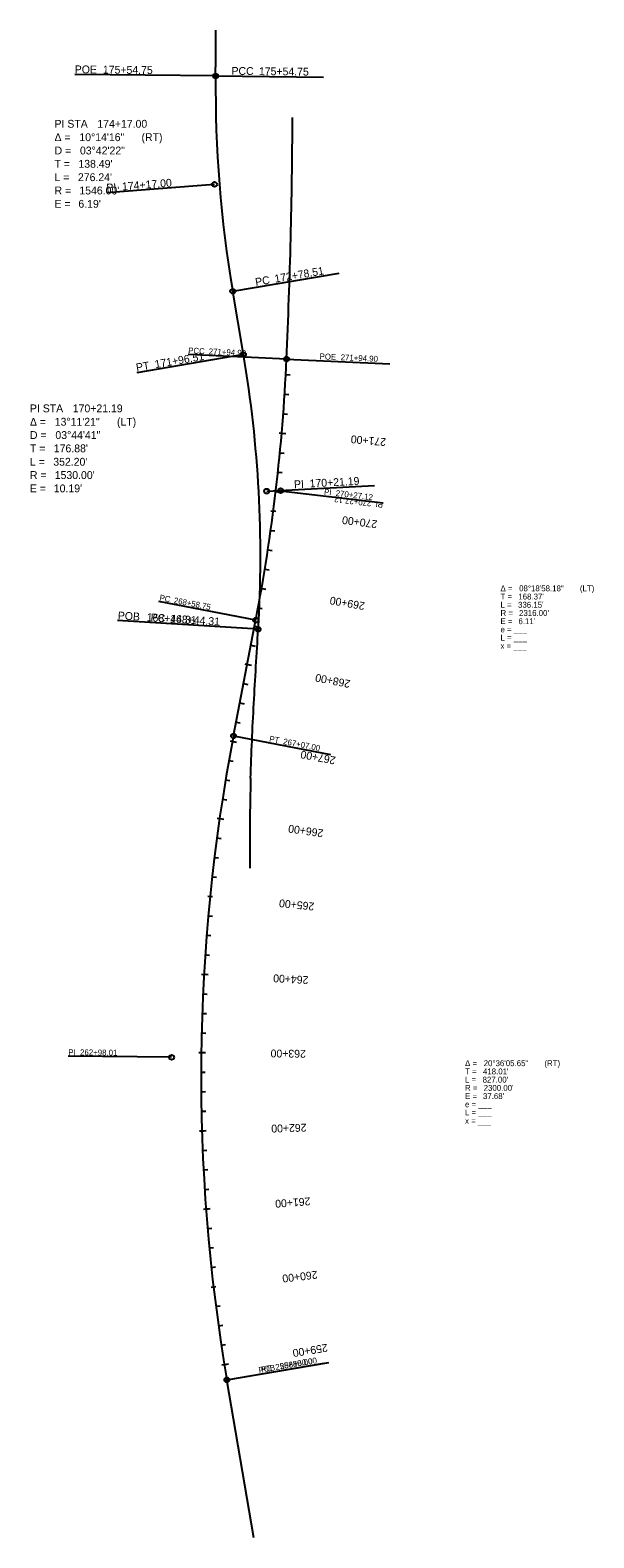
# Model space of a CAD drawing. Extents: x 11526303 to 11527023, y 9594193 to 9596119.
import ezdxf

# ---------------------------------------------------------------- set-up
doc = ezdxf.new("R2010")
doc.units = 0
for name, color, linetype in [('Alignment', 7, 'Continuous'), ('Default', 7, 'Continuous'), ('Draft_2', 7, 'Continuous'), ('Draft_5', 7, 'Continuous'), ('TextAlignment', 7, 'Continuous'), ('TextAlignmentLrg', 7, 'Continuous'), ('TextAlignmentSml', 7, 'Continuous')]:
    doc.layers.add(name, color=color, linetype=linetype)

msp = doc.modelspace()

# ---------------------------------------------------------------- linework, layer by layer
at = {"layer": 'Alignment'}
for p, q in [((11526575.7, 9595704.1), (11526562, 9595785)), ((11526563, 9595217), (11526591.6, 9595366))]:
    msp.add_line(p, q, dxfattribs=at)
for centre, radius, start, end in [((11528086.1, 9596044.3), 1546, 179.4211, 189.6588), ((11525067.4, 9595447.4), 1530, 356.4695, 9.6588), ((11524317.1, 9595802.4), 2316, 349.1117, 357.4279), ((11528821.6, 9594782.5), 2300, 169.1117, 189.7133)]:
    msp.add_arc(centre, radius, start, end, dxfattribs=at)
at = {"layer": 'Default'}
msp.add_line((11526589.1, 9594192.7), (11526554.5, 9594394.5), dxfattribs=at)
for centre, radius, start, end in [((11518903.1, 9596137.1), 7637.4, 359.42082, 359.86053), ((11518997, 9596041.3), 7641.4, 357.42787, 359.74097), ((11529462.5, 9595081), 2878.8, 178.3649, 180.6529)]:
    msp.add_arc(centre, radius, start, end, dxfattribs=at)
msp.add_open_spline([(11526584.9, 9595163.1), (11526585.4, 9595179), (11526586.5, 9595210.7), (11526588.9, 9595258.3), (11526591.6, 9595305.8), (11526593.6, 9595337.5), (11526594.5, 9595353.3)], degree=3, dxfattribs=at)
at = {"layer": 'Draft_2'}
msp.add_line((11526563, 9595217), (11526591.6, 9595366), dxfattribs=at)
msp.add_arc((11528821.6, 9594782.5), 2300, 169.1117, 189.7133, dxfattribs=at)
at = {"layer": 'Draft_5'}
msp.add_line((11526563, 9595217), (11526591.6, 9595366), dxfattribs=at)
for centre, radius, start, end in [((11524317.1, 9595802.4), 2316, 349.1117, 357.4279), ((11528821.6, 9594782.5), 2300, 169.1117, 189.7133)]:
    msp.add_arc(centre, radius, start, end, dxfattribs=at)
at = {"layer": 'TextAlignment'}
for p, q in [((11526540.2, 9596060), (11526360.2, 9596061.8)), ((11526360.2, 9596061.8), (11526360.2, 9596061.8)), ((11526540.2, 9596060), (11526678.1, 9596058.6)), ((11526678.1, 9596058.6), (11526678.1, 9596058.6)), ((11526538.8, 9595921.5), (11526401.2, 9595910.6)), ((11526401.2, 9595910.6), (11526401.2, 9595910.6)), ((11526562, 9595785), (11526698, 9595808.1)), ((11526698, 9595808.1), (11526698, 9595808.1)), ((11526575.7, 9595704.1), (11526439.7, 9595681)), ((11526630.8, 9595698.4), (11526504.9, 9595704.1)), ((11526504.9, 9595704.1), (11526504.9, 9595704.1)), ((11526630.8, 9595698.4), (11526762.7, 9595692.5)), ((11526439.7, 9595681), (11526439.7, 9595681)), ((11526762.7, 9595692.5), (11526762.7, 9595692.5)), ((11526605.4, 9595529.7), (11526743.2, 9595537.1)), ((11526623.2, 9595530.2), (11526754.3, 9595514.7)), ((11526623.2, 9595530.2), (11526754.3, 9595514.7)), ((11526743.2, 9595537.1), (11526743.2, 9595537.1)), ((11526754.3, 9595514.7), (11526754.3, 9595514.7)), ((11526754.3, 9595514.7), (11526754.3, 9595514.7)), ((11526591.4, 9595364.9), (11526467.7, 9595388.7)), ((11526467.7, 9595388.7), (11526467.7, 9595388.7)), ((11526594.5, 9595353.2), (11526414.9, 9595364.3)), ((11526414.9, 9595364.3), (11526414.9, 9595364.3)), ((11526594.5, 9595353.2), (11526456.8, 9595361.7)), ((11526456.8, 9595361.7), (11526456.8, 9595361.7)), ((11526563, 9595217), (11526686.7, 9595193.2)), ((11526686.7, 9595193.2), (11526686.7, 9595193.2)), ((11526484, 9594806.5), (11526352, 9594807.9)), ((11526352, 9594807.9), (11526352, 9594807.9)), ((11526484, 9594806.5), (11526352, 9594807.9)), ((11526352, 9594807.9), (11526352, 9594807.9)), ((11526554.5, 9594394.5), (11526684.7, 9594416.8)), ((11526554.5, 9594394.5), (11526678.7, 9594415.7)), ((11526678.7, 9594415.7), (11526678.7, 9594415.7)), ((11526684.7, 9594416.8), (11526684.7, 9594416.8))]:
    msp.add_line(p, q, dxfattribs=at)
for centre, radius in [((11526540.2, 9596060), 3.12), ((11526540.2, 9596060), 2.67), ((11526538.8, 9595921.5), 3.12), ((11526562, 9595785), 3.12), ((11526575.7, 9595704.1), 3.12), ((11526630.8, 9595698.4), 3.12), ((11526630.8, 9595698.4), 2.67), ((11526605.4, 9595529.7), 3.12), ((11526623.2, 9595530.2), 3.12), ((11526623.2, 9595530.2), 3.12), ((11526591.4, 9595364.9), 3.12), ((11526594.5, 9595353.2), 3.12), ((11526594.5, 9595353.2), 2.67), ((11526563, 9595217), 3.12), ((11526484, 9594806.5), 3.12), ((11526484, 9594806.5), 3.12), ((11526554.5, 9594394.5), 3.12), ((11526554.5, 9594394.5), 2.67)]:
    msp.add_circle(centre, radius, dxfattribs=at)
at = {"layer": 'TextAlignmentLrg'}
for p, q in [((11526624.6, 9595603.7), (11526630, 9595603.3)), ((11526610.8, 9595504.7), (11526616.9, 9595503.9)), ((11526598.9, 9595405.4), (11526604.2, 9595404.5)), ((11526580.5, 9595308.3), (11526585.9, 9595307.3)), ((11526561.7, 9595210.1), (11526567, 9595209.1)), ((11526545.2, 9595111.5), (11526550.6, 9595110.7)), ((11526530, 9595012.5), (11526536.1, 9595011.9)), ((11526525.3, 9594912.6), (11526530.7, 9594912.2)), ((11526521.8, 9594812.6), (11526527.2, 9594812.5)), ((11526522.6, 9594712.6), (11526528.1, 9594712.8)), ((11526527.8, 9594612.8), (11526533.3, 9594613.2)), ((11526534.4, 9594512.9), (11526540.4, 9594513.6)), ((11526551.3, 9594414.2), (11526556.6, 9594415.1))]:
    msp.add_line(p, q, dxfattribs=at)
at = {"layer": 'TextAlignmentSml'}
for p, q in [((11526629.8, 9595678.5), (11526635.3, 9595678.2)), ((11526628.3, 9595653.6), (11526633.8, 9595653.2)), ((11526626.6, 9595628.6), (11526632, 9595628.2)), ((11526621.5, 9595604), (11526627.6, 9595603.5)), ((11526622.3, 9595578.8), (11526627.7, 9595578.3)), ((11526619.8, 9595554), (11526625.2, 9595553.4)), ((11526616.9, 9595529.1), (11526622.4, 9595528.5)), ((11526610.8, 9595504.7), (11526616.9, 9595503.9)), ((11526610.5, 9595479.5), (11526615.9, 9595478.8)), ((11526606.9, 9595454.8), (11526612.3, 9595454)), ((11526603, 9595430.1), (11526608.4, 9595429.2)), ((11526595.8, 9595406), (11526601.9, 9595404.9)), ((11526594.4, 9595380.8), (11526599.8, 9595379.8)), ((11526590, 9595357.4), (11526595.4, 9595356.4)), ((11526585.3, 9595332.9), (11526590.6, 9595331.8)), ((11526577.5, 9595308.9), (11526583.6, 9595307.7)), ((11526575.8, 9595283.8), (11526581.2, 9595282.7)), ((11526571.1, 9595259.2), (11526576.5, 9595258.2)), ((11526566.4, 9595234.7), (11526571.7, 9595233.6)), ((11526558.7, 9595210.7), (11526564.7, 9595209.6)), ((11526557.2, 9595185.5), (11526562.5, 9595184.6)), ((11526552.9, 9595160.9), (11526558.3, 9595160)), ((11526548.9, 9595136.2), (11526554.3, 9595135.4)), ((11526542.2, 9595111.9), (11526548.3, 9595111.1)), ((11526541.8, 9595086.7), (11526547.2, 9595086)), ((11526538.6, 9595061.9), (11526544, 9595061.3)), ((11526535.7, 9595037.1), (11526541.1, 9595036.5)), ((11526530, 9595012.5), (11526536.1, 9595011.9)), ((11526530.7, 9594987.4), (11526536.2, 9594986.9)), ((11526528.6, 9594962.4), (11526534.1, 9594962)), ((11526526.8, 9594937.5), (11526532.3, 9594937.1)), ((11526522.2, 9594912.7), (11526528.3, 9594912.4)), ((11526524, 9594887.6), (11526529.4, 9594887.3)), ((11526523, 9594862.6), (11526528.4, 9594862.4)), ((11526522.2, 9594837.6), (11526527.7, 9594837.5)), ((11526518.7, 9594812.7), (11526524.8, 9594812.6)), ((11526521.6, 9594787.6), (11526527, 9594787.6)), ((11526521.7, 9594762.6), (11526527.1, 9594762.7)), ((11526522, 9594737.6), (11526527.5, 9594737.7)), ((11526519.6, 9594712.5), (11526525.7, 9594712.7)), ((11526523.5, 9594687.6), (11526529, 9594687.9)), ((11526524.7, 9594662.7), (11526530.2, 9594663)), ((11526526.1, 9594637.7), (11526531.6, 9594638.1)), ((11526524.8, 9594612.6), (11526530.9, 9594613)), ((11526529.8, 9594587.9), (11526535.3, 9594588.3)), ((11526532.1, 9594563), (11526537.5, 9594563.5)), ((11526534.6, 9594538.1), (11526540, 9594538.7)), ((11526534.4, 9594512.9), (11526540.4, 9594513.6)), ((11526540.5, 9594488.4), (11526545.9, 9594489.1)), ((11526543.8, 9594463.7), (11526549.2, 9594464.4)), ((11526547.4, 9594438.9), (11526552.8, 9594439.7)), ((11526548.2, 9594413.7), (11526554.3, 9594414.7))]:
    msp.add_line(p, q, dxfattribs=at)

# ---------------------------------------------------------------- texts
at = {"layer": 'TextAlignment'}
for s, height, rotation, p in [('POE ', 10.02, 359.4211, (11526360.2, 9596063.5)), ('175+54.75', 10.02, 359.4211, (11526396.1, 9596063.1)), ('PCC', 10.02, 359.4211, (11526560.4, 9596061.5)), ('175+54.75', 10.02, 359.4211, (11526595.4, 9596061.1)), ('174+17.00', 10.02, 4.5399, (11526421, 9595913.8)), ('PI ', 10.02, 4.5399, (11526401.1, 9595912.2)), ('172+78.51', 10.02, 9.6588, (11526616.2, 9595795.9)), ('PC', 10.02, 9.6588, (11526591.6, 9595791.7)), ('171+96.51', 10.02, 9.6588, (11526463.3, 9595686.7)), ('PCC', 7.5, 357.4279, (11526505, 9595705.7)), ('271+94.90', 7.5, 357.4279, (11526531.2, 9595704.5)), ('POE ', 7.5, 357.4279, (11526672.8, 9595698.2)), ('271+94.90', 7.5, 357.4279, (11526699.7, 9595697)), ('PT', 10.02, 9.6588, (11526439.4, 9595682.6)), ('PI ', 10.02, 3.0641, (11526640.5, 9595533.3)), ('170+21.19', 10.02, 3.0641, (11526660.4, 9595534.4)), ('PI ', 7.5, 353.2698, (11526678.3, 9595525.4)), ('270+27.12', 7.5, 353.2698, (11526693.2, 9595523.6)), ('270+27.12', 7.5, 173.2698, (11526739.6, 9595517.5)), ('PI ', 7.5, 173.2698, (11526754.4, 9595515.8)), ('PC', 7.5, 349.1117, (11526468, 9595390.3)), ('268+58.75', 7.5, 349.1117, (11526486.3, 9595386.8)), ('POB ', 10.02, 356.4695, (11526415, 9595366)), ('168+44.31', 10.02, 356.4695, (11526451.9, 9595363.7)), ('PC', 10.02, 356.4695, (11526456.9, 9595363.4)), ('168+44.31', 10.02, 356.4695, (11526481.8, 9595361.9)), ('PT', 7.5, 349.1117, (11526608.2, 9595210)), ('267+07.00', 7.5, 349.1117, (11526626, 9595206.6)), ('PI ', 7.5, 359.4125, (11526352, 9594809.2)), ('PI ', 7.5, 359.4125, (11526352, 9594809.2)), ('262+98.01', 7.5, 359.4125, (11526367, 9594809.1)), ('262+98.01', 7.5, 359.4125, (11526367, 9594809.1)), ('POB ', 7.5, 9.7133, (11526595.7, 9594403.2)), ('PC', 7.5, 9.7133, (11526598.8, 9594403.7)), ('258+80.00', 7.5, 9.7133, (11526617.2, 9594406.9)), ('258+80.00', 7.5, 9.7133, (11526623, 9594407.9))]:
    msp.add_text(s, height=height, rotation=rotation, dxfattribs=at).set_placement(p)
for s, height, p in [('Δ = ', 10.02, (11526334.4, 9595976.8)), ('PI STA ', 10.02, (11526334.4, 9595993.9)), ('10°14\'16"', 10.02, (11526366.1, 9595976.8)), ('174+17.00', 10.02, (11526389.1, 9595993.9)), (' (RT)', 10.02, (11526441.8, 9595976.8)), ('D = ', 10.02, (11526334.4, 9595959.8)), ('03°42\'22"', 10.02, (11526366.9, 9595959.8)), ('T = ', 10.02, (11526334.4, 9595942.8)), ("138.49'", 10.02, (11526364.9, 9595942.8)), ('L = ', 10.02, (11526334.4, 9595925.7)), ("276.24'", 10.02, (11526364.3, 9595925.7)), ('R = ', 10.02, (11526334.4, 9595908.7)), ("1546.00'", 10.02, (11526366.1, 9595908.7)), ('E = ', 10.02, (11526334.4, 9595891.7)), ("6.19'", 10.02, (11526364.9, 9595891.7)), ('PI STA ', 10.02, (11526303, 9595630.4)), ('170+21.19', 10.02, (11526357.7, 9595630.4)), ('Δ = ', 10.02, (11526303, 9595613.3)), ('13°11\'21"', 10.02, (11526334.7, 9595613.3)), (' (LT)', 10.02, (11526410.4, 9595613.3)), ('D = ', 10.02, (11526303, 9595596.3)), ('03°44\'41"', 10.02, (11526335.5, 9595596.3)), ('T = ', 10.02, (11526303, 9595579.3)), ("176.88'", 10.02, (11526333.5, 9595579.3)), ('L = ', 10.02, (11526303, 9595562.2)), ("352.20'", 10.02, (11526332.8, 9595562.2)), ('R = ', 10.02, (11526303, 9595545.2)), ("1530.00'", 10.02, (11526334.7, 9595545.2)), ('E = ', 10.02, (11526303, 9595528.2)), ("10.19'", 10.02, (11526333.5, 9595528.2)), ('Δ = ', 7.5, (11526904, 9595401.8)), ('08°18\'58.18"', 7.5, (11526927.8, 9595401.8)), (' (LT)', 7.5, (11527002.6, 9595401.8)), ('T = ', 7.5, (11526904, 9595391.3)), ("168.37'", 7.5, (11526926.8, 9595391.3)), ('L = ', 7.5, (11526904, 9595380.8)), ('R = ', 7.5, (11526904, 9595370.3)), ("336.15'", 7.5, (11526926.4, 9595380.8)), ("2316.00'", 7.5, (11526927.7, 9595370.3)), ('e = ___ ', 7.5, (11526904, 9595349.3)), ('E = ', 7.5, (11526904, 9595359.8)), ("6.11'", 7.5, (11526926.9, 9595359.8)), ('x = ___', 7.5, (11526904, 9595328.3)), ('L = ___', 7.5, (11526904, 9595338.8)), ('Δ = ', 7.5, (11526858.7, 9594795.2)), ('20°36\'05.65"', 7.5, (11526882.5, 9594795.2)), (' (RT)', 7.5, (11526957.3, 9594795.2)), ('T = ', 7.5, (11526858.7, 9594784.7)), ('L = ', 7.5, (11526858.7, 9594774.2)), ("827.00'", 7.5, (11526881.1, 9594774.2)), ("418.01'", 7.5, (11526881.6, 9594784.7)), ('R = ', 7.5, (11526858.7, 9594763.7)), ('E = ', 7.5, (11526858.7, 9594753.2)), ("37.68'", 7.5, (11526881.6, 9594753.2)), ("2300.00'", 7.5, (11526882.5, 9594763.7)), ('e = ___ ', 7.5, (11526858.7, 9594742.7)), ('L = ___', 7.5, (11526858.7, 9594732.2)), ('x = ___', 7.5, (11526858.7, 9594721.7))]:
    msp.add_text(s, height=height, dxfattribs=at).set_placement(p)
at = {"layer": 'TextAlignmentLrg'}
for s, rotation, p in [('270+00', 172.6062, (11526747.1, 9595492.1)), ('265+00', 174.2683, (11526666.6, 9595003.9)), ('260+00', 186.7239, (11526669.6, 9594533.9))]:
    msp.add_text(s, height=10.02, rotation=rotation, dxfattribs=at).set_placement(p)
at = {"layer": 'TextAlignmentSml'}
for s, rotation, p in [('271+00', 175.0801, (11526758.2, 9595597.2)), ('270+00', 172.6062, (11526747.1, 9595492.1)), ('269+00', 170.1322, (11526731.4, 9595387.5)), ('268+00', 169.1117, (11526712.8, 9595288)), ('267+00', 169.2861, (11526694, 9595190.2)), ('266+00', 171.7772, (11526678.3, 9595097.3)), ('265+00', 174.2683, (11526666.6, 9595003.9)), ('264+00', 176.7595, (11526659, 9594910)), ('263+00', 179.2506, (11526655.5, 9594815.9)), ('262+00', 181.7417, (11526656.1, 9594721.7)), ('261+00', 184.2328, (11526660.8, 9594627.6)), ('260+00', 186.7239, (11526669.6, 9594533.9)), ('259+00', 189.2151, (11526682.4, 9594440.6))]:
    msp.add_text(s, height=10.02, rotation=rotation, dxfattribs=at).set_placement(p)

doc.saveas('drawing.dxf')
